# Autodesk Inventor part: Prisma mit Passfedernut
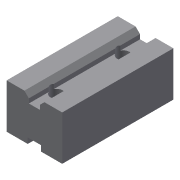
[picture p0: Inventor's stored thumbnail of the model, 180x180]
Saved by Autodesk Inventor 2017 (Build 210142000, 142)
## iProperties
Created: 2015-06
Part Number: Prisma mit Passfedernut
Material: Generisch
Document SubType Name: Modeling
Designer: e_krauts
Density: 1 g/cm^3
Appearance: Vorgabe
Author: e_krauts
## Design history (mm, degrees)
sketch "Skizze2"
  geometry: L1 (-12.5, 0)-(12.5, 0) reference; L2 (-12.5, 20)-(-12.5, 0) reference; L3 (0, 7)-(0, -1.145) reference; L4 (-3, 0)-(-3, 2.5); L5 (-3, 2.5)-(3, 2.5); L6 (3, 2.5)-(3, 0); 1 further point
  constraints: 8 end point, 2 parallel, 2 perpendicular, 2 point on line, 1 vertical, 1 other
  dimensions: "d17" = 6 distance between parallel lines of L6 L4; "d18" = 2.5 distance between parallel lines of L1 L5
extrude "Extrusion1" new body sketch "Skizze2" stored distance "d13" = 50; taper "d14" = 0 deg
extrude "Extrusion2" cut sketch "Skizze2" stored distance "d19" = 50; taper "d20" = 0 deg
sketch "Skizze4"
  geometry: L1 (8, -50)-(0, -50) reference; L2 (-4.5, 3)-(-4.5, -65); L3 (-22, -25)-(16, -25) reference; 3 further points
  constraints: 4 end point, 2 perpendicular, 2 point on line, 1 horizontal, 1 symmetric about line
  dimensions: "d21" = 30 distance of point (-4.5, -40) point (-4.5, -10)
hole "Bohrung1" sketch "Skizze4" at (-4.5, -10), (-4.5, -40) diameter "d22" = 2.9; stored, may be unused: countersink angle "d26" = 90 deg, drill point angle "d28" = 118 deg; dims "d23" = 6, "d24" = 5.5, "d25" = 10, "d27" = 8
sketch "Skizze5"
  geometry: L1 (-12.5, 0)-(12.5, 0) reference; L2 (-12.5, 20)-(-12.5, 0) reference; L3 (0, 3.75)-(0, -3) reference; L4 (-4, 0)-(-4, -2.25); L5 (-4, -2.25)-(4, -2.25); L6 (4, -2.25)-(4, 0); 1 further point
  constraints: 8 end point, 3 parallel, 2 point on line, 1 perpendicular, 1 vertical, 1 other
  dimensions: "d29" = 8 distance between parallel lines of L6 L4; "d30" = 2.25 distance between parallel lines of L1 L5
extrude "Extrusion3" join sketch "Skizze5" stored distance "d31" = 10; taper "d32" = 0 deg
sketch "Skizze6"
  geometry: L1 (8, -50)-(0, -50) reference; L2 (10, -27.5)-(-19.574, -27.5); 2 further points
  constraints: 2 end point, 1 coincident, 1 parallel
hole "Bohrung2" sketch "Skizze6" at (-4.5, -25) diameter "d33" = 2.9; stored, may be unused: countersink angle "d37" = 90 deg, drill point angle "d39" = 118 deg; dims "d34" = 6, "d35" = 5.5, "d36" = 10, "d38" = 8
node "Volumenkörper1"
sketch "Skizze1"
  geometry: L1 (0, 0)-(0, 56) reference; L2 (0, 0)-(-12.5, 0); L3 (-12.5, 0)-(-12.5, 20); L4 (-12.5, 20)-(-4.5, 20); L5 (-4.5, 20)-(-2.5, 18); L6 (-2.5, 18)-(-2.5, 16); L7 (-2.5, 16)-(0, 16); L8 (0, 0)-(12.5, 0); L9 (12.5, 0)-(12.5, 20); L10 (12.5, 20)-(4.5, 20); L11 (4.5, 20)-(2.5, 18); L12 (2.5, 18)-(2.5, 16); L13 (2.5, 16)-(0, 16)
  constraints: 26 end point, 5 symmetric about line, 3 perpendicular, 2 parallel, 2 vertical, 1 point on line
  dimensions: "d7" = 5 diameter of L6 L1; "d8" = 4 distance between parallel lines of L7 L4; "d9" = 2 distance from line of L7 L5.end; "d10" = 45 deg angle of L1 L5; "d11" = 25 diameter of L3 L1; "d12" = 20 distance between parallel lines of L2 L4
